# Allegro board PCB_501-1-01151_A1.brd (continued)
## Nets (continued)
SD1_CD#_R: R87.2 U6.J14
SD1_CLK: C93.1 J2.5 P5.2 R81.2
SD1_CLK_R: R81.1 U6.C1
SD1_CMD: J2.3 P6.2 R72.2 R82.2
SD1_CMD_R: R82.1 U6.C2
SD1_DATA0: R73.2 R107.1 U6.B3
SD1_DATA1: R74.2 R108.1 U6.B2
SD1_DATA2: R75.2 R105.1 U6.B1
SD1_DATA3: R76.2 R106.1 U6.A2
SD1_VSEL: R33.1 R35.1 R37.1 U4.B1
SD2_CLK: R71.2 U8.M6
SD2_CMD: R102.2 R830.1 U6.C8
SD2_DATA0: R94.2 R822.1 U6.D7
SD2_DATA1: R95.2 R823.1 U6.B7
SD2_DATA2: R96.2 R824.1 U6.A7
SD2_DATA3: R97.2 R825.1 U6.D6
SD2_DATA4: R98.2 R826.1 U6.C6
SD2_DATA5: R99.2 R827.1 U6.B6
SD2_DATA6: R100.2 R828.1 U6.A6
SD2_DATA7: R829.1 R858.2 U6.A5
SD2_RESET#: R101.2 U6.B4 U8.K5
SD2_STROBE: R103.2 U8.H5
SD_VSEL_R: R33.2 U6.D1
SDCARD_DAT0: J2.7 P4.2 R107.2
SDCARD_DAT1: J2.8 P3.2 R108.2
SDCARD_DAT2: J2.1 P8.2 R105.2
SDCARD_DAT3: J2.2 P7.2 R106.2
ST_HUB_LEDA1#: R150.1 U14.51
ST_HUB_LEDA2#: R151.1 U14.49
ST_HUB_LEDA3#: R153.1 U14.47
ST_HUB_LEDA4#: R157.1 U14.33
ST_HUB_LEDA5#: R158.1 U14.31
ST_QSPIA_SCLK: R809.1 U6.D5
ST_SD2_CLK: R71.1 U6.D8
STBY_REQ: Q41.3 R763.1 U1.26
SYS_BU: C33.1 U1.24
SYS_NRST: C599.1 D27.2 D28.2 R833.2 R874.2 U26.3
TOUCH_BUSY: R199.1 U6.G14
TOUCH_CLOCK: U6.E4 U24.16
TOUCH_CS#: R201.1 U6.E3
TOUCH_INTR_REQ#: U6.H15 U24.11
TOUCH_MISO: U6.E1 U24.12
TOUCH_MOSI: U6.E2 U24.14
TOUCH_X+: C191.2 R198.1 U24.2
TOUCH_X-: C192.2 R200.1 U24.4
TOUCH_XL: J9.38 R200.2
TOUCH_XR: J9.36 R198.2
TOUCH_Y+: C193.2 R202.1 U24.3
TOUCH_Y-: C194.2 R203.1 U24.5(Y-)
TOUCH_YD: J9.37 R203.2
TOUCH_YU: J9.39 R202.2
TPS2054_OC1#: R155.1 R816.1 U18.16
TPS2054_OC2#: R156.1 R817.1 U18.13
TPS2054_OC3#: R159.1 R818.1 U18.12
TPS2054_OC4#: R160.1 R819.1 U18.9
TXLED: D10.1(K) U20.7
UART1_CTS#: R832.2 U6.K15
UART1_RX_DATA: R167.1 R169.2 U6.K16
UART1_TX_DATA: R170.2 U6.K14
USB2ANY_I2C_SCL: H1.9 R875.2
USB2ANY_I2C_SDA: H1.10 R876.1
USB_HOST_DN: U6.T13 U14.58
USB_HOST_DP: U6.U13 U14.59
USB_HOST_ID: R770.2 U6.M17
USB_LDO_DECAP: C97.1 C98.1 U6.R12
USB_OTG1_CHD#: TP33.1 U6.U16
USB_OTG1_DN: FL6.1 U6.T15
USB_OTG1_DP: FL6.4 U6.U15
USB_OTG1_FAULT#: R86.2 U6.L15 U19.3
USB_OTG1_ID: J7.4 U6.K13 U17.4 U17.7
USB_OTG1_PWREN: R164.2 R166.1 U6.M16 U19.4
USBDM_FL1: FL1.2 J4.2 U15.5 U15.6
USBDM_FL2: FL2.2 J4.6 U15.2 U15.9
USBDM_FL3: FL3.2 J5.2 U16.5 U16.6
USBDM_FL4: FL4.2 J5.6 U16.2 U16.9
USBDM_FL5: FL5.2 J6.2 P15.2
USBDN: C176.1 R172.2 U20.9
USBDN1_DM: FL1.1 U14.1
USBDN1_DP: FL1.4 U14.2
USBDN2_DM: FL2.1 U14.3
USBDN2_DP: FL2.4 U14.4
USBDN3_DM: FL3.1 U14.6
USBDN3_DP: FL3.4 U14.7
USBDN4_DM: FL4.1 U14.8
USBDN4_DP: FL4.4 U14.9
USBDN5_DM: FL5.1 U14.11
USBDN5_DP: FL5.4 U14.12
USBDP: C175.1 R171.2 U20.8
USBDP_FL1: FL1.3 J4.3 U15.4 U15.7
USBDP_FL2: FL2.3 J4.7 U15.1 U15.10(NC4)
USBDP_FL3: FL3.3 J5.3 U16.4 U16.7
USBDP_FL4: FL4.3 J5.7 U16.1 U16.10(NC4)
USBDP_FL5: FL5.3 J6.3 P14.2
USR_B0: R872.2 SW4.2
USR_B1: R873.2 SW5.2
USR_BT0: C195.1 R204.2 R872.1 U6.F2
USR_BT1: C196.1 R208.2 R873.1 U6.F3
USR_LED1: R205.2 U6.D4
USR_LED2: R206.2 U6.D3
USR_LED3: R207.2 U6.D2
VREF_TOUCH_C: C189.2 U24.9
WDOG_ANY: R771.2 U6.M15 U27.2
X1_ENETPHY: R132.2 U10.70
XTALI: C204.1 R263.2 R821.2 U6.T16 X3.3
XTALIN_HUB: C129.1 R148.1 U14.61 X1.1
XTALO: C205.1 R263.1 U6.T17 X3.1
XTALOUT_HUB: C130.1 R148.2 U14.60 X1.3
N20222589: D5.2 R7.1
N20248573: R34.1 U4.A1
N20257520: R62.1 U7.L9
N20264538: FB16.2 J2.COM1 J2.COM2
N20269907: R17.2 R803.2 U2.4(Y)
N20274074: FB5.1 J8.5
N20274097: J8.4 R173.1
N20280334: D10.2 R176.2
N20280345: D11.2 R177.2
N20323615: R130.1 R133.1 Y1.1
N20326291: J3.32 R116.2
N20327026: D7.2 R109.2
N20327568: J3.28 R131.2
N20327935: D8.2 R124.2
N20368037: FB15.2 J7.5
N20387129: R225.1 SW6.5
N20387131: R226.1 SW6.6
N20387133: R227.1 SW6.7
N20387143: R232.1 SW6.8
N20387145: R575.2 SW7.4
N20387147: R576.2 SW7.3
N20429331: D28.1(K) R771.1 U27.4(Y)
N20436944: J3.1 J3.2 J3.3 J3.4 J3.8 J3.9 J3.10 R121.2
N20467513: R578.2 R579.1 U26.5
N20496187: J3.17 J3.18 J3.19(TRD4-[2]) J3.20 J3.24 J3.25 J3.26 R135.2
N20630241: DA8.3 R782.2
N20681531: C591.2 R790.2 R791.1 R810.1
N20684634: C592.2 R792.2 R793.1 R811.1
N20685468: C593.2 R794.2 R795.1 R812.1
N20685796: C594.2 R796.2 R797.1 R813.1
N20829804: D29.1(K) R266.2
N20866761: J3.33 R120.1
N20868982: J3.29 R134.2

Pads without a net: FD1 1; FD2 1; FD3 1; FD4 1; FD5 1; FD6 1; FD7 1; FD8 1; FD9 1; FD10 1; FD11 1; FD12 1; H1 1 2 3 4 5 7 8; J9 1 9 32 35; U1 28 29 34; U6 P16 P17; U8 A1 A2 A7 A8 A9 A10 A11 A12 A13 A14 B1 B7 B8 B9 B10 B11 B12 B13 B14 C1 C3 C5 C7 C8 C9 C10 C11 C12 C13 C14 D1 D2 D3 D4 D12 D13 D14 E1 E2 E3 E5 E8 E9 E10 E12 E13 E14 F1 F2 F3 F10 F12 F13 F14 G1 G2 G3 G10 G12 G13 G14 H1 H2 H3 H12 H13 H14 J1 J2 J3 J12 J13 J14 K1 K2 K3 K6 K7 K10 K12 K13 K14 L1 L2 L3 L12 L13 L14 M1 M2 M3 M7 M8 M9 M10 M11 M12 M13 M14 N1 N3 N6 N7 N8 N9 N10 N11 N12 N13 N14 P1 P2 P7 P8 P9 P10 P11 P12 P13 P14; U10 3 8 12 16 17 45 46 50 59 63 69 72 73 74 75 76 79; U14 14 15 16 17 18 32 36 37 38 39; U20 16; U22 8 9 10 13; U23 8 9 10 13; U24 8

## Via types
v1: diameter 0.457, hole 0.203, TOP to BOTTOM, 1517 vias

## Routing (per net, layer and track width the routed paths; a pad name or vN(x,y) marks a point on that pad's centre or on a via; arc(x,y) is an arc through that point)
3V3_OUT: length 2.2
  BOTTOM w0.142: R168.2 11.03,43.3 11.05,43.3 11.25,43.5 U20.10
5VIN: length 6.8
  TOP w0.381: R6.1 18.11,80.77 19.3,81.96 19.3,82.8 ; 22.61,88.77 22.75,88.77 R1.2 24.1,89.52 24.13,89.49 Q2.2
GND: length 1338.5
  TOP w0.076: U8.A6 73.8,24.06 73.77,24.06 ; U8.N5 79.72,23.63 79.32,23.63 v1(78.93,24.02) ; U8.N2 79.72,21.65 79.72,20.96
  TOP w0.142: U21.C2 8.31,41.33 v1(8.38,41.4) ; v1(79.72,20.83) 79.72,20.96 ; U8.K8 78.86,24.89 v1(78.99,25.02) ; U6.J5 v1(63.81,41.37) ; v1(73.15,25.08) 73.15,24.68 73.77,24.06
  TOP w0.178: P1.1 19.34,80.52 v1(19.32,80.49)
  TOP w0.203: v1(75.45,23.38) 75.45,23.37 U8.C4 ; v1(81.98,24.13) 81.07,24.13 80.83,23.89 U8.P6 U8.N5 ; v1(81.22,22.89) U8.P4 ; v1(61.41,38.97) 61.02,38.58 U6.E8 v1(60.61,38.97) ; v1(76.84,22.86) 76.97,22.99 U8.G5 ; v1(29.34,39.24) 29.45,39.24 29.6,39.39 U3.C1 ; v1(77.98,22.87) 77.97,22.88 U8.J5 ; U8.H10 v1(77.47,26.35) ; v1(76.71,24.77) 76.63,24.68 76.47,24.68 76.18,24.39 U8.E7 ; U4.C1 v1(92.07,22.48) ; U5.C1 v1(32.38,84.58) ; P14.1 46.72,83.29 v1(46.58,83.14) ; v1(60.61,44.6) 61,44.21 U6.M8 61.29,44.47 61.51,44.47 U6.M7 ; v1(46.41,85.33) 46.55,85.18 P15.1
  TOP w0.254: U7.T1 v1(77.81,33.61) ; U6.R16 v1(54.18,47) ; U6.U1 67.26,48.18 67.31,48.13 v1(67.31,48.17) ; v1(53.72,48.64) 53.72,48.26 U6.U17 ; U6.N7 v1(62.21,45.4) ; U6.L12 v1(57.38,43.8) ; U6.T14 v1(55.78,47.8) ; v1(78.36,79.12) U15.3 U15.8 v1(80.65,79.12) ; v1(59.81,38.97) U6.F10 59.26,39.24 58.74,39.24 U6.F11 58.6,39.29 58.42,39.11 58.06,39.11 57.8,39.38 U6.F12 v1(57.38,38.97) ; U7.P1 v1(77.81,35.21) ; U7.D8 v1(84.21,44) ; v1(59.69,79.25) U16.8 U16.3 v1(62.1,79.25) ; U7.G1 v1(77.81,41.6) ; U6.R7 v1(62.21,47) ; U6.K7 v1(62.21,43) ; U6.E11 v1(58.18,38.17) ; U7.G9 v1(85.01,41.6) ; U26.2 v1(91.69,81.91) ; U7.G8 v1(84.21,41.6) ; U6.M9 v1(60.61,44.6) ; U7.M9 v1(85.01,36.81) ; U6.G3 v1(65.41,39.77) ; v1(5.46,30.99) U17.8 U17.3 v1(5.46,28.58) ; U6.G5 v1(63.81,39.77) ; U6.M11 58.21,44.57 v1(58.16,44.57) 57.8,44.21 U6.M12 ; U7.J2 v1(78.61,39.21) ; U6.C7 v1(62.21,36.57) ; U6.H7 v1(62.21,40.57) ; U6.N3 v1(65.41,45.4) ; U6.L3 v1(65.41,43.8) ; U7.E8 v1(84.21,43.2) ; U6.G7 v1(62.21,39.77) ; v1(53.45,46.97) 53.47,46.96 53.47,46.91 U6.R17 ; U7.D1 v1(77.81,44) ; U7.M1 v1(77.81,36.81) ; U6.R11 v1(58.18,47) ; U6.M7 v1(62.21,44.6) ; U6.R3 v1(65.41,47) ; U6.F9 v1(60.61,38.97) ; U6.A1 v1(66.99,34.99) ; U6.C3 v1(65.41,36.57) ; U6.A17 v1(53.38,34.97) ; U6.F7 v1(62.21,38.97) ; U6.U14 v1(55.78,48.6) ; U7.E2 v1(78.61,43.2) ; U6.J7 v1(62.21,41.37) ; U6.L7 v1(62.21,43.8) ; U7.B1 v1(77.81,45.6) ; U7.B9 v1(85.01,45.6) ; U6.H12 57.77,40.98 v1(57.38,41.37) U6.J12 ; U7.E1 v1(77.81,43.2) ; U6.F6 v1(63.01,38.97) ; U7.J8 v1(84.21,39.21) ; U6.N5 v1(63.81,45.4) ; U6.C11 v1(58.18,36.57) ; U6.M10 v1(58.98,44.6) ; U14.19 v1(67.27,72.09) ; U6.K12 v1(57.38,43) ; U26.6 v1(92.19,80.01) ; U7.B3 v1(79.41,45.6) ; U6.G15 v1(54.98,39.77) ; U6.G12 v1(57.38,39.77) ; U6.F8 v1(61.41,38.97) ; U7.P9 v1(85.01,35.21) ; U6.R5 v1(62.98,47) ; U6.C15 v1(54.98,36.57) ; U7.F9 v1(85.01,42.4) ; U7.A9 v1(85.01,46.4) ; U7.T9 v1(85.01,33.61)
  TOP w0.305: v1(46.22,48.14) 46.1,48.26 C9.2 ; C18.2 45.8,49.4 46.08,49.69 v1(46.13,49.69)
  TOP w0.381: 76.61,57.75 C589.2 v1(76.71,56.52) ; 76.61,57.75 76.07,57.21 v1(76.07,56.64) ; 76.61,57.75 v1(75.6,57.75) ; C115.2 v1(96.14,18.41) ; H4.11 19.72,43.94 v1(20.32,44.55) ; v1(51.16,61.99) 51.67,62.5 R15.1 ; 1.4,22.34 J7.S4 v1(4.26,22.34) ; H4.17 v1(19.94,40.13) ; C3.2 26.01,71.6 v1(26.39,71.22) ; v1(28.45,73.91) C4.2 v1(27.43,75.02) ; SW8.1 98.75,79.07 v1(98.55,78.87) ; TP32.1 v1(43.43,76.2) ; SW4.3 v1(97.1,54.03) ; R851.1 R852.1 v1(13.97,61.85) ; v1(52.07,60.07) 52.07,60.02 52.32,59.77 52.32,59.47 C23.2 53.09,59.65 v1(53.09,60.07) ; v1(21.46,71.22) 19.3,71.22 C590.2 ; v1(35.81,58.84) C24.2 v1(37.71,58.84) ; R62.2 v1(89.41,38.1) ; H4.13 19.37,42.67 19.73,42.32 v1(19.79,42.32) ; R149.2 v1(80.42,63.25) ; v1(75.69,63.12) 75.69,63 75.16,62.46 R152.2 ; C33.2 v1(38.48,62.87) ; SW3.1 v1(96.47,73.99) ; v1(82.8,80.77) 83.08,80.5 83.25,80.5 ; C41.2 v1(29.21,84.71) 29.08,84.58 28.32,84.58 27.82,84.08 D5.1 ; R146.2 v1(71.25,58.01) ; C177.2 v1(4.06,47.12) ; v1(79.4,56.69) 79.74,57.03 C597.2 ; C114.2 97.41,20.07 97.72,20.38 v1(97.72,21.4) ; R178.2 v1(2.79,47.12) ; C599.2 v1(94.74,82.8) ; R253.1 v1(45.59,26.19) ; v1(40.01,19.56) 40.02,19.54 C116.2 v1(40.89,18.8) ; R14.2 v1(39.75,68.96) ; C591.1 37.21,18.16 v1(37.47,17.91) ; C588.2 v1(20.96,44.96) ; C598.2 95.87,77.62 v1(95.25,78.23) ; v1(33.02,84.96) 33.66,84.33 C43.2 ; X3.4 50.11,54.65 v1(49.66,55.1) ; C190.2 64.79,16.24 v1(64.9,16.13) ; U2.3 53.99,60.06 53.84,60.21 v1(53.72,60.21) ; R16.2 v1(54.74,64.17) ; C126.2 v1(40.89,22.86) ; D1.2 v1(23.88,91.69) ; v1(36.55,13.57) 36.6,13.62 ; v1(79.4,58.34) 79.74,58 C597.2 ; v1(50.8,49.15) 50.67,49.15 50.55,49.28 C8.2 C7.2 ; DA1.4 v1(91.04,97.93) ; H5.8 v1(1.9,59.31) ; R770.1 v1(43.43,39.24) ; v1(59.05,8.64) 59.56,8.13 C184.2 ; C586.2 v1(22.1,47.75) ; R154.2 67.18,61.91 67.13,61.86 67.13,61.67 v1(66.93,61.47) ; C186.2 v1(68.58,3.56) ; v1(4.32,24.65) J7.S3 1.41,24.65 ; v1(36.96,60.85) C29.2 37.36,61.34 37.2,61.34 37.17,61.37 37.05,61.37 v1(36.96,61.46) ; R254.1 v1(50.16,26.19) ; R843.1 v1(92.84,69.85) ; v1(46.77,26.23) 46.74,26.19 R260.1 ; C129.2 v1(78.94,73.3) ; J7.S2 v1(4.26,19.74) ; Q3.2 v1(14.84,80.12) ; R127.1 v1(45.59,18.92) ; R19.2 v1(54.48,64.87) ; C198.2 v1(84.47,8.15) ; v1(49.53,66.8) 48.96,66.23 C19.2 v1(49.78,65.79) ; v1(96.01,75.44) 96.27,75.69 SW3.3 ; v1(93.6,22.23) 93.49,22.34 C39.2 ; H4.15 v1(19.94,41.4) ; v1(30.1,75.06) C5.2 v1(30.84,75.8) ; R63.1 v1(89.41,36.96) ; C11.2 36.39,49.66 v1(36.29,49.56) ; C34.2 v1(37.57,55.12) ; C95.2 C94.2 56.75,51.82 56.37,52.2 v1(56.26,52.2) ; C36.2 v1(31.48,41.55) ; v1(30.05,38.27) 30.4,38.27 30.52,38.16 30.55,38.16 30.63,38.08 R805.2 ; v1(22.86,61.85) 22.1,61.09 H1.6 ; J7.S1 v1(4.26,27.25) ; H5.12 v1(1.9,64.39) ; C20.2 v1(48.77,67.44) ; H5.16 v1(1.9,69.47) ; C21.2 v1(50.42,55.63) ; C127.2 v1(42.04,22.86) ; C195.2 v1(92.71,52.2) ; H5.4 v1(1.9,54.23) ; H5.14 1.8,66.93 1.78,66.95 v1(1.71,66.95) ; v1(37.64,23.95) 37.31,24.29 C593.1 ; v1(41.58,68.59) C31.2 v1(40.81,68.8) ; DA2.4 v1(72.12,97.93) ; v1(76.71,75.22) 76.71,74.11 R577.1 ; C130.2 v1(78.21,69.86) ; C583.2 v1(23.24,52.2) ; v1(88.26,80.52) 88.52,80.77 C573.2 ; C183.2 C187.2 C185.2 C182.2 v1(62.48,3.43) ; C32.2 v1(37.08,65.58) ; R848.1 v1(12.85,73.15) ; v1(43.69,71.12) C30.2 v1(42.76,70.14) ; R259.1 v1(49.02,26.19) ; C572.2 v1(3.67,48.24) ; v1(95.12,81.03) 94.62,81.53 R579.2 ; R37.2 90.91,19.79 v1(91.06,19.94) ; SW4.1 v1(97.41,51.39) ; v1(95.88,58.42) 96.7,57.61 SW5.1 ; v1(1.56,61.83) 1.65,61.83 1.67,61.85 H5.10 ; C164.2 v1(62.74,71.63) ; C120.2 50.99,17.67 v1(51.05,17.61) 51.63,17.61 51.68,17.56 C117.2 ; R144.2 v1(71.88,61.6) ; R258.1 v1(47.88,26.19) ; C93.2 71.37,31.6 v1(70.87,31.1) ; TP30.1 v1(86.76,74.29) ; H4.19 v1(19.94,38.86) ; SW2.3 v1(96.01,69.72) ; FB15.1 v1(4.59,16.87) ; C596.2 v1(30.48,84.71) ; U27.3 v1(93.08,89.52) ; v1(55.88,52.7) 55.31,52.7 54.97,53.05 X3.2 53.69,52.65 C204.2 ; C22.2 52.67,56.37 v1(52.7,56.34) ; H5.6 v1(1.9,56.77) ; Q17.2 19.23,54.17 v1(19.81,53.59) ; R58.2 v1(89.41,40.39) ; C197.2 v1(78.36,3.43) ; R60.2 v1(89.41,39.24) ; R257.1 v1(43.31,26.19) ; FB5.2 v1(9.56,37.47) ; R256.1 v1(44.45,26.19) ; C597.2 v1(78.99,57.53) ; C174.2 v1(7.33,44.79) ; DA3.4 v1(68.69,97.93) ; SW2.1 v1(96.44,68.02) ; C35.2 v1(34.18,41.55) ; v1(95.76,82.55) 95.76,81.98 96.08,81.66 SW8.3 ; DA5.4 v1(36.94,97.93) ; DA8.4 v1(24.98,53.3) ; R255.1 v1(51.31,26.19) ; v1(56.52,54.61) 55.73,53.83 R821.1 ; C161.2 v1(62.71,65.02) ; C162.2 v1(62.71,67.31) ; C584.2 v1(22.1,50.67) ; v1(88.9,25.27) 89.05,25.42 C40.2 C42.2 v1(91.83,25.42) ; DA4.4 v1(49.64,97.93) ; H5.18 v1(1.9,72.01) ; C10.2 v1(36.29,50.93) ; R145.2 v1(70.76,60.22) ; v1(94.33,25.4) FB16.1 v1(94.98,26.05) ; v1(92.84,58.8) 93.34,59.31 C196.2 ; H5.20 v1(1.9,74.55) ; C587.2 v1(22.1,44.96) ; R17.1 v1(57.02,57.15) ; C585.2 v1(22.1,48.9) ; R173.2 v1(9.56,38.61) ; R135.1 v1(24.51,37.72) ; v1(50.93,50.93) 50.57,51.28 C205.2 ; C38.2 v1(28.32,42.29) ; TP31.1 v1(42.8,5.84) ; SW5.3 v1(95.88,59.31) ; C199.2 v1(79.5,3.43) ; R9.1 v1(14.08,76.33) ; C1.2 v1(17.14,81.9) ; C163.2 v1(62.74,69.34)
  TOP w0.508: J3.S2 26.89,24.37 ; J3.S2 25.3,22.79 ; J3.S2 28.47,22.79 ; 73.75,87.32 J4.S4 ; J4.S4 73.75,91.74 ; J4.S4 75.96,89.53 ; 78.79,70.51 C130.2 77.64,70.51 ; J6.S3 44.12,82.41 ; J6.S3 42.69,80.98 ; J6.S3 45.56,80.98 ; H5.18 6.4,72.01 ; H5.18 4.26,71.07 ; H5.18 4.26,72.95 ; J6.S1 44.12,89.41 ; J6.S1 44.12,86.54 ; J6.S1 45.56,87.98 ; J6.S1 42.69,87.98 ; 77.65,73.3 C129.2 78.22,73.87 ; 5.01,86.11 J1.2 ; J1.2 7.63,86.11 ; J1.2 6.32,88.48 ; J1.2 6.32,83.73 ; J6.S2 38.68,89.41 ; J6.S2 40.12,87.98 ; J6.S2 38.68,86.54 ; 86.89,86.06 J4.S2 86.89,81.64 ; MH5.1 36.07,78.6 ; MH5.1 38.47,76.2 ; MH5.1 36.07,73.8 ; MH5.1 33.67,76.2 ; H5.12 6.4,64.39 ; H5.12 4.26,65.33 ; H5.12 4.26,63.45 ; 64.54,87.32 J5.S3 ; J5.S3 62.33,89.53 ; J5.S3 66.75,89.53 ; J5.S3 64.54,91.74 ; 40.32,81.25 J6.4 ; J6.4 42.48,81.25 ; J6.4 41.4,80.17 ; 86.89,87.32 J4.S3 ; J4.S3 84.68,89.53 ; J4.S3 89.1,89.53 ; J4.S3 86.89,91.74 ; 95.4,18.99 C115.2 95.4,17.84 ; 83.25,80.5 C601.1 ; C601.1 84.39,80.5 ; C601.1 83.82,79.93 ; 1.49,27.25 J7.S1 2.75,28.71 ; 28.36,94.16 TP56.1 ; TP56.1 27.04,96.37 ; TP56.1 28.36,98.58 ; TP56.1 29.68,96.37 ; 5.59,16.3 FB15.1 6.16,16.87 ; J3.S3 26.89,8.01 ; J3.S3 25.3,6.43 ; J3.S3 28.47,6.43 ; 4.64,46.25 C177.2 3.49,46.25 ; 91.44,5.07 MH6.1 89.04,2.67 ; 89.04,76.2 MH7.1 ; MH7.1 91.44,73.8 ; MH7.1 93.84,76.2 ; 73.75,86.06 J4.S1 73.75,81.64 ; J3.S4 11.68,6.43 ; J3.S4 10.1,8.01 ; J3.S4 8.51,6.43 ; 96.71,19.1 C114.2 96.05,20.07 ; 64.54,81.64 J5.S2 ; J5.S2 64.54,86.06 ; J5.S2 66.75,83.85 ; 4.26,60.91 H5.10 ; H5.10 4.26,62.79 ; H5.10 6.4,61.85 ; J5.8 55.55,86.82 ; J5.8 54.47,85.74 ; J5.8 54.47,87.9 ; J5.8 53.39,86.82 ; J3.S1 11.68,22.79 ; J3.S1 10.1,24.37 ; J3.S1 8.51,22.79 ; 41.78,5.03 TP31.1 ; TP31.1 41.78,6.66 ; TP31.1 40.97,5.84 ; 83.57,8.72 C198.2 82.99,8.15 ; 7.33,42.75 C174.2 6.54,43.56 ; 21.59,94.6 SW1.S2 ; SW1.S2 22.88,96.27 ; SW1.S2 21.59,97.93 ; 48.03,67.86 C20.2 48.03,67.02 ; 36.57,13.72 C592.1 37.14,14.29 ; 93.49,23.94 C39.2 94.06,23.37 ; 76.59,74.56 R577.1 77.16,73.99 ; J4.8 76.82,87.9 ; J4.8 75.74,86.82 ; J4.8 77.9,86.82 ; J4.8 76.82,85.74 ; 4.26,68.53 H5.16 ; H5.16 6.4,69.47 ; H5.16 4.26,70.41 ; H5.8 6.4,59.31 ; H5.8 4.26,60.25 ; H5.8 4.26,58.37 ; 4.32,47.67 C572.2 4.89,48.24 ; MH8.1 38.47,2.67 ; MH8.1 33.67,2.67 ; MH8.1 36.07,5.07 ; 39.33,69.7 R14.2 40.17,69.7 ; 19.49,97.4 SW1.3 19.49,95.14 ; J1.S2 5.32,91.91 ; J1.S2 5.32,89.3 ; J1.S2 2.77,90.61 ; J1.S2 7.87,90.61 ; H5.6 4.26,57.71 ; H5.6 6.4,56.77 ; H5.6 4.26,55.83 ; H5.20 4.26,75.49 ; H5.20 4.26,73.61 ; H5.20 6.4,74.55 ; 87.58,73.19 TP30.1 86.76,72.38 ; 42.16,77.01 TP32.1 42.16,75.39 ; 1.49,19.74 J7.S2 2.75,18.28 ; J1.S1 7.87,81.61 ; J1.S1 5.32,82.91 ; J1.S1 2.77,81.61 ; J1.S1 5.32,80.3 ; 49.19,83.85 J5.S1 ; J5.S1 51.4,81.64 ; J5.S1 51.4,86.06 ; 17.49,97.4 SW1.2 17.49,95.14 ; 12.11,96.27 SW1.S1 ; SW1.S1 13.39,94.6 ; SW1.S1 13.39,97.93 ; 29.78,83.97 C41.2 28.64,83.97 ; J6.S4 40.12,80.98 ; J6.S4 38.68,82.41 ; J6.S4 38.68,79.54 ; 76.82,85.28 J4.4 76.82,83.12 ; J5.S4 51.4,91.74 ; J5.S4 51.4,87.32 ; J5.S4 53.61,89.53 ; 27.82,83.06 D5.1 28.63,83.82 ; 3.37,46.25 R178.2 2.22,46.25 ; 6.4,66.93 H5.14 4.26,67.87 ; 54.47,85.28 J5.4 54.47,83.12 ; H5.4 4.26,55.17 ; H5.4 6.4,54.23 ; H5.4 4.26,53.29 ; 13.42,64.39 R851.1 12.85,64.96 ; 36.21,29.72 C594.1 36.79,29.15 ; 40.81,67.16 C31.2 41.44,67.82
  L2_GND w0.508: J5.S4 53.61,89.53 ; J5.S4 51.4,91.74 ; J5.S4 49.19,89.53 ; J5.S4 51.4,87.32 ; 96.77,5.36 MH2.1 94.72,3.3 ; J5.8 55.55,86.82 ; J5.8 53.39,86.82 ; J5.8 54.47,87.9 ; J5.8 54.47,85.74 ; 71.54,89.53 J4.S4 ; J4.S4 73.75,91.74 ; J4.S4 73.75,87.32 ; J4.S4 75.96,89.53 ; 91.44,74.64 MH7.1 ; MH7.1 91.44,77.76 ; MH7.1 93,76.2 ; MH7.1 89.88,76.2 ; 44.12,79.54 J6.S3 ; J6.S3 42.69,80.98 ; J6.S3 45.56,80.98 ; J6.S3 44.12,82.41 ; J4.S1 73.75,86.06 ; J4.S1 73.75,81.64 ; J4.S1 71.54,83.85 ; J6.S4 38.68,82.41 ; J6.S4 37.25,80.98 ; J6.S4 40.12,80.98 ; J6.S4 38.68,79.54 ; J4.4 77.9,84.2 ; J4.4 76.82,83.12 ; J4.4 76.82,85.28 ; 41.4,80.17 J6.4 ; J6.4 40.32,81.25 ; J6.4 42.48,81.25 ; 25.3,22.79 J3.S2 ; J3.S2 26.89,21.2 ; J3.S2 28.47,22.79 ; J3.S2 26.89,24.37 ; J1.2 7.63,86.11 ; J1.2 6.32,83.73 ; J1.2 6.32,88.48 ; J1.2 5.01,86.11 ; 8.51,22.79 J3.S1 ; J3.S1 11.68,22.79 ; J3.S1 10.1,21.2 ; J3.S1 10.1,24.37 ; 37.25,87.98 J6.S2 ; J6.S2 40.12,87.98 ; J6.S2 38.68,89.41 ; J6.S2 38.68,86.54 ; J3.S3 28.47,6.43 ; J3.S3 25.3,6.43 ; J3.S3 26.89,8.01 ; J3.S3 26.89,4.84 ; J3.S4 10.1,8.01 ; J3.S4 10.1,4.84 ; J3.S4 11.68,6.43 ; J3.S4 8.51,6.43 ; 89.88,2.67 MH6.1 ; MH6.1 91.44,4.23 ; MH6.1 93,2.67 ; MH5.1 36.07,77.76 ; MH5.1 36.07,74.64 ; MH5.1 34.51,76.2 ; MH5.1 37.63,76.2 ; 5.32,89.3 J1.S2 ; J1.S2 2.77,90.61 ; J1.S2 7.87,90.61 ; J1.S2 5.32,91.91 ; 3.18,94.72 MH1.1 5.23,96.77 ; 34.51,2.67 MH8.1 ; MH8.1 36.07,4.23 ; MH8.1 37.63,2.67 ; 5.23,3.3 MH3.1 3.18,5.36 ; 96.77,94.72 MH4.1 94.72,96.77 ; 62.33,89.53 J5.S3 ; J5.S3 64.54,91.74 ; J5.S3 66.75,89.53 ; J5.S3 64.54,87.32 ; 42.69,87.98 J6.S1 ; J6.S1 44.12,86.54 ; J6.S1 44.12,89.41 ; J6.S1 45.56,87.98 ; 17.49,95.36 SW1.2 ; SW1.2 17.49,97.17 ; SW1.2 18.4,96.27 ; SW1.2 16.59,96.27 ; J4.S3 89.1,89.53 ; J4.S3 86.89,91.74 ; J4.S3 86.89,87.32 ; J4.S3 84.68,89.53 ; SW1.S2 22.84,96.27 ; SW1.S2 21.59,95.02 ; SW1.S2 21.59,97.51 ; 51.4,81.64 J5.S1 ; J5.S1 51.4,86.06 ; J5.S1 49.19,83.85 ; J4.S2 86.89,86.06 ; J4.S2 89.1,83.85 ; J4.S2 86.89,81.64 ; J5.4 55.55,84.2 ; J5.4 54.47,85.28 ; J5.4 54.47,83.12 ; J5.S2 64.54,86.06 ; J5.S2 64.54,81.64 ; J5.S2 66.75,83.85 ; 19.49,95.36 SW1.3 ; SW1.3 18.59,96.27 ; SW1.3 19.49,97.17 ; J4.8 77.9,86.82 ; J4.8 75.74,86.82 ; J4.8 76.82,85.74 ; J4.8 76.82,87.9 ; 5.32,80.3 J1.S1 ; J1.S1 7.87,81.61 ; J1.S1 5.32,82.91 ; J1.S1 2.77,81.61 ; SW1.S1 13.39,97.51 ; SW1.S1 12.15,96.27 ; SW1.S1 13.39,95.02
  L3_SIG1 w0.508: 2.77,81.61 J1.S1 ; J1.S1 5.32,82.91 ; J1.S1 5.32,80.3 ; J1.S1 7.87,81.61 ; 2.77,90.61 J1.S2 ; J1.S2 5.32,91.91 ; J1.S2 7.87,90.61 ; J1.S2 5.32,89.3 ; J1.2 7.63,86.11 ; J1.2 6.32,88.48 ; J1.2 6.32,83.73 ; J1.2 5.01,86.11
  L4_SIG2 w0.508: 6.32,83.73 J1.2 ; J1.2 5.01,86.11 ; J1.2 6.32,88.48 ; J1.2 7.63,86.11 ; J1.S2 5.32,91.91 ; J1.S2 7.87,90.61 ; J1.S2 5.32,89.3 ; J1.S2 2.77,90.61 ; 5.32,80.3 J1.S1 ; J1.S1 7.87,81.61 ; J1.S1 2.77,81.61 ; J1.S1 5.32,82.91
  L5_PWR w0.381: v1(96.65,22.22) 95.16,22.22 94.95,22.01
  L5_PWR w0.508: MH6.1 91.44,4.23 ; MH6.1 89.88,2.67 ; MH6.1 93,2.67 ; 5.32,89.3 J1.S2 ; J1.S2 7.87,90.61 ; J1.S2 5.32,91.91 ; J1.S2 2.77,90.61 ; 25.3,22.79 J3.S2 ; J3.S2 28.47,22.79 ; J3.S2 26.89,24.37 ; J3.S2 26.89,21.2 ; 6.32,83.73 J1.2 ; J1.2 7.63,86.11 ; J1.2 5.01,86.11 ; J1.2 6.32,88.48 ; J3.S1 11.68,22.79 ; J3.S1 8.51,22.79 ; J3.S1 10.1,24.37 ; J3.S1 10.1,21.2 ; 10.1,4.84 J3.S4 ; J3.S4 10.1,8.01 ; J3.S4 11.68,6.43 ; J3.S4 8.51,6.43 ; 25.3,6.43 J3.S3 ; J3.S3 26.89,8.01 ; J3.S3 28.47,6.43 ; J3.S3 26.89,4.84 ; 5.23,3.3 MH3.1 3.18,5.36 ; J1.S1 7.87,81.61 ; J1.S1 5.32,82.91 ; J1.S1 2.77,81.61 ; J1.S1 5.32,80.3 ; 34.51,2.67 MH8.1 ; MH8.1 36.07,4.23 ; MH8.1 37.63,2.67 ; 96.77,5.36 MH2.1 94.72,3.3
  BOTTOM w0.142: v1(58.18,47) 58.33,47 58.75,47.42 59.27,47.42 59.59,47.1 C60.2
  BOTTOM w0.178: P5.1 v1(88.39,27.43) ; P7.1 v1(85.72,27.43) ; P4.1 v1(89.66,27.43) ; P8.1 v1(84.33,27.43) ; P6.1 v1(87,27.43) ; P3.1 v1(91.06,27.43)
  BOTTOM w0.203: J9.40 54,6.05 v1(53.85,6.2) ; P10.1 82.8,79.08 v1(82.38,79.08) ; C577.2 47.77,13.09 47.72,13.15 U10.6 47.72,14.9 47.68,14.93 v1(47.68,15.08) ; v1(51.05,17.61) 51.21,17.45 U10.77 ; P2.1 v1(81.03,18.41) ; v1(40.01,19.56) 39.61,19.95 U10.29 ; P9.1 v1(93.7,85.85) ; v1(57.01,78.64) 57.2,78.82 P12.1 ; U10.33 39.73,21.95 v1(40.01,22.23) ; U10.22 v1(40.07,16.45)
  BOTTOM w0.254: v1(53.45,46.97) 53.44,46.99 53.34,46.99 53.09,46.74 C56.2 ; U13.2 U13.1 ; U13.2 U13.3 ; U13.2 83.69,61.22 ; U13.1 84.19,60.72 83.69,61.22 ; U13.1 v1(84.19,59.18) ; U10.55 47.72,28.42 v1(47.75,28.45) ; v1(45.47,15.37) 45.72,15.12 U10.10 ; C122.1 U11.8 U11.3 v1(31.75,16.26) ; U13.3 v1(83.19,59.18) ; U13.3 83.19,61.22 ; U13.3 U13.4 82.69,60.72 83.19,61.22 ; J9.6 71,4.03 71.02,4.01 71.02,3.7 71.21,3.51 v1(71.21,3.21) ; v1(70.61,3.34) 70.61,3.85 70.5,3.96 J9.7 ; U10.64 53.02,23.95 v1(53.2,24.13) ; P11.1 60.12,78.82 v1(59.69,79.25) ; C61.2 61.31,47.1 v1(61.41,47) ; U10.29 37.96,19.95 37.57,20.34 C575.2 ; v1(73.81,72.92) 73.81,73.2 C138.2 ; v1(73.91,3.89) 73.27,3.89 73.05,4.11 73.05,4.3 73.04,4.31 73.04,4.41 73,4.46 J9.2 ; 83.19,61.22 v1(83.44,61.47) 83.69,61.22 ; v1(54.18,47) 54.1,46.91 C55.2 ; J9.4 72.04,4.99 72.04,4.12 72.14,4.03 72.14,3.4 v1(72.26,3.27) ; U10.37 v1(37.64,23.95) ; v1(46.77,26.23) 46.42,26.23 46.22,26.43 U10.52 ; v1(71.63,3.82) 71.5,3.95 J9.5 ; v1(57.38,39.77) 57.43,39.82 C91.2 ; v1(83.67,65) C128.2 83.67,63.59 83.69,63.57 U13.7 ; U12.8 v1(31.24,27.94) ; v1(69.74,3.3) 70,3.56 J9.8 ; U10.40 39.68,25.45 v1(39.88,25.65) ; P13.1 v1(45.59,76.2) ; U20.5 v1(16.18,44.77) ; U10.25 v1(39.96,17.95) ; U12.3 v1(28.58,27.94)
  BOTTOM w0.305: v1(73.66,69.47) 73.91,69.72 C140.2 ; C139.2 v1(70.1,72.26) ; C142.2 v1(72.52,72.26) ; C143.2 v1(73.79,68.2) ; C135.2 v1(67.82,67.82) ; v1(30.99,49.78) 30.99,49.25 31.19,49.05 U22.3 ; U23.3 v1(32.08,69.92) ; C136.2 v1(67.82,68.96) ; C141.2 v1(73.79,67.06) ; R147.2 v1(68.58,72.26)
  BOTTOM w0.381: C72.2 62.88,47.1 v1(62.98,47) ; C574.2 v1(47.64,29.98) ; C607.2 v1(59.27,15.25) ; C605.1 44.01,75.62 v1(43.43,76.2) ; R238.1 63.01,11.7 v1(63.22,11.91) ; R246.1 73.79,14.62 74.17,15.01 v1(74.17,15.11) ; v1(53.45,18.54) 53.54,18.45 Y1.2 v1(54.64,19.84) ; C134.2 v1(73.53,70.99) ; C189.1 65.15,19.61 64.77,19.23 v1(64.77,18.92) ; R64.1 v1(80.39,35.69) ; v1(55.7,10.49) 55.63,10.41 C192.1 ; U9.4 70.75,30.99 v1(70.87,31.1) ; R251.1 v1(77.34,13.84) ; R572.2 v1(51.31,10.54) ; C121.2 v1(44.72,29.86) ; C201.2 v1(60.38,54.03) ; C85.2 85.06,33.55 v1(85.01,33.61) ; R197.2 v1(80.26,11.16) ; v1(43.56,74.8) 43.56,74.04 TP42.1 ; v1(57.38,38.97) 57.65,38.71 C47.2 58.01,38.34 v1(58.18,38.17) ; R239.1 v1(63.25,10.92) ; C109.2 81.21,22.88 v1(81.22,22.89) ; v1(57.53,81.41) 57.53,80.72 57.48,80.67 C604.1 ; v1(59.05,8.64) R194.2 ; v1(47.99,66.44) R24.1 R21.2 ; C172.2 v1(20.96,38.99) ; v1(35.13,38.48) 33.79,38.48 33.51,38.76 R569.1 ; C92.2 65.68,36.3 v1(65.41,36.57) 65.91,37.06 C96.2 ; v1(65.41,39.77) 65.89,39.77 66.06,39.6 C68.2 C67.2 ; v1(96.27,67.18) 95.88,67.56 C149.2 ; C180.2 v1(32.66,50.31) ; R129.2 v1(34.06,20.96) ; R248.1 v1(75.06,15.37) ; C153.2 v1(87.08,70.19) ; v1(96.14,60.07) 96.05,60.16 U18.1 ; v1(85.01,36.81) 85.11,36.91 C63.2 ; v1(70.37,46.27) 70.21,46.1 C54.2 ; C125.1 v1(7.73,29.73) ; C78.2 85.06,46.46 v1(85.01,46.4) ; R242.1 70.41,14.91 70.76,15.27 v1(70.76,15.29) ; U20.13 10.77,45.4 10.43,45.74 C171.2 10.16,46.23 v1(9.91,46.48) ; v1(62.21,39.77) C69.2 v1(62.21,40.57) 62.13,40.65 62.13,40.95 C52.2 62.14,41.3 v1(62.21,41.37) 62.12,41.46 C51.2 62.12,42.91 v1(62.21,43) v1(62.21,43.8) C70.2 v1(62.21,44.6) ; v1(62.21,38.97) 62.39,38.79 C90.2 ; R808.2 v1(81.03,12.45) ; v1(4.95,50.42) C37.2 5.7,51.03 4.01,52.71 4.01,57.61 BH1.2 ; C77.2 85.11,41.5 v1(85.01,41.6) ; R773.1 51.17,37.19 v1(50.87,37.49) ; C575.2 v1(36.32,20.34) ; R240.1 68.83,14.75 v1(68.83,15.37) ; v1(65.49,50.21) 65.66,50.04 C88.2 ; v1(77.85,2.57) 77.62,2.33 J9.M1 75.6,2.8 v1(76.53,3.73) ; C49.2 v1(49.38,42.16) ; R245.1 v1(72.64,13.84) ; C158.2 v1(95.88,58.42) ; C193.1 v1(53.72,9.8) ; Q41.2 v1(33.81,64.45) ; U19.6 52.96,71.75 v1(53.34,72.14) ; v1(62.23,16.64) 62.02,16.85 U24.6 ; R236.1 v1(61.6,10.92) ; C156.2 v1(83.69,67.31) ; v1(77.81,35.21) 77.37,34.77 C74.2 ; v1(29.21,84.71) 29.44,84.94 R806.2 ; v1(77.98,22.87) 77.98,22.86 78.21,22.63 C108.2 ; C603.1 60.11,80.13 60.11,80.88 v1(60.16,80.93) ; v1(30.21,37.59) 30.23,37.59 30.61,37.97 R836.2 ; R247.1 v1(74.29,13.84) ; v1(82.17,25.15) 82.15,25.17 C107.2 ; C191.1 v1(57.91,10.45) ; v1(56.26,52.2) 56.62,51.84 C97.2 C98.2 ; R121.1 v1(14.73,23.88) ; v1(9.3,40.93) 9.58,40.65 9.69,40.65 ; C83.2 77.41,46 v1(77.81,45.6) ; R241.1 v1(69.6,13.97) ; R174.1 21.72,43.56 v1(21.75,43.59) ; C131.2 v1(67.94,71.25) ; C168.2 v1(53.78,69.78) ; C124.1 v1(6.98,27.69) ; R65.2 65.88,45.87 v1(65.41,45.4) ; v1(77.81,41.6) 77.55,41.87 77.55,41.87 77.43,41.98 77.43,41.98 77.36,42.06 C64.2 ; C576.2 v1(36.34,21.57) ; C76.2 83.54,42.27 v1(84.21,41.6) ; C154.2 v1(87.86,71.39) ; C104.2 79.01,25 v1(78.99,25.02) ; v1(55.78,48.6) v1(55.78,47.8) ; R772.2 30.48,41.29 v1(30.84,41.66) ; v1(58.16,44.57) 58.18,44.6 C53.2 v1(58.98,44.6) 59.11,44.47 C45.2 60.48,44.47 v1(60.61,44.6) ; R252.1 v1(78.87,14.62) ; C200.2 60.4,50.56 60.81,50.56 v1(61.13,50.88) ; v1(85.01,42.4) 85.17,42.57 C80.2 ; v1(65.41,43.8) 66.38,43.8 C71.2 ; C87.2 v1(67.72,52.83) ; R249.1 v1(75.82,13.84) ; C155.2 v1(85.09,66.54) ; C122.1 28.85,16.74 28.7,16.89 v1(28.7,16.9) ; C166.2 v1(49.78,77.09) ; C133.2 v1(67.94,70.1) ; v1(50.62,39.53) 50.87,39.77 R779.1 ; v1(60.48,49.67) 60.28,49.47 C59.2 ; C73.2 65.55,47.14 v1(65.41,47) ; v1(77.47,26.35) 77.43,26.31 C105.2 ; C112.2 C113.2 78.38,28.09 v1(78.68,28.39) ; v1(76.71,24.77) 76.79,24.68 77,24.68 77.28,24.4 C103.2 ; C86.2 80.11,45.37 79.87,45.6 v1(79.41,45.6) ; C28.2 37.67,61.63 v1(37.65,61.65) ; C167.1 v1(48.01,75.95) ; v1(84.21,39.21) 84.22,39.22 C75.2 ; v1(81.91,82.04) 81.91,80.54 82.41,80.04 C602.1 ; v1(63.81,41.37) 63.77,41.41 C66.2 ; C62.2 57.4,43.82 v1(57.38,43.8) ; v1(39.37,65.23) 39.97,65.23 40.86,64.34 C600.2 ; C157.2 v1(95.88,57.28) ; C137.2 v1(73.53,66.33) ; C6.2 v1(37.97,54.48) ; v1(60.61,38.97) 60.61,38.98 59.86,39.73 C50.2 59.82,38.98 v1(59.81,38.97) 59.94,38.84 C46.2 ; J2.6 93.85,21.98 v1(93.6,22.23) ; v1(50.75,4.01) 51.9,2.86 J9.M2 50.04,2.33 v1(49.78,2.59) ; v1(39.37,55.37) 38.82,55.92 C15.2 ; v1(11.59,50.22) 12.26,49.55 R179.1 ; C102.2 C99.2 52.34,41.04 v1(51.84,40.53) ; v1(48.48,45.76) C44.2 v1(47.5,44.83) 46.97,44.3 R832.1 ; TP41.1 v1(88,49.27) ; C79.2 83.72,44.49 v1(84.21,44) ; C170.2 8.15,45.74 v1(8,45.59) ; C160.2 v1(91.19,58.17) ; C89.2 53.34,35.01 v1(53.38,34.97) ; C123.1 v1(21.59,23.88) ; U18.5 v1(89.79,61.34) ; C48.2 59.37,33.3 v1(59.37,33.09) 58.8,32.52 TP51.1 ; v1(77.81,36.81) 77.68,36.68 C81.2 ; C82.2 77.34,43.66 77.57,43.43 77.58,43.43 v1(77.81,43.2) ; C119.2 54.46,24.15 54.87,23.73 v1(54.87,23.12) ; C159.2 v1(91.19,57.02) ; C58.2 C57.2 54.23,50.67 v1(53.98,50.93) ; R103.1 v1(76.84,22.86) ; v1(85.01,45.6) 85.58,45.6 85.59,45.59 85.6,45.59 85.85,45.34 C84.2 ; R133.2 v1(56.39,12.07) ; U22.5 v1(32.76,47.62) ; C101.2 C100.2 v1(52.39,44.85) ; C181.2 v1(30.25,69.96) ; TP43.1 v1(47,5.73) ; R243.1 v1(71.12,13.84) ; C152.2 v1(90.04,69.09) ; C169.1 53.33,66.8 v1(53.72,67.19) ; C151.2 v1(89.27,67.56) ; v1(4.32,24.65) 4.44,24.77 C606.1 ; R244.1 v1(71.88,15.27) ; C118.2 v1(45.61,11.83) ; R68.1 v1(67.7,51.84) ; C165.2 v1(49.17,72.24) ; R815.1 35.79,40.69 v1(34.84,41.65) ; v1(75.45,23.38) 75.48,23.35 C106.2 ; C150.2 v1(95.25,69.22) ; C175.2 v1(16.28,40.53) ; R574.2 v1(52.07,30.51) ; C110.2 v1(77.34,18.41) ; C577.2 47.77,11.83 v1(47.75,11.81) ; C14.2 v1(43.31,57.4) ; C132.2 v1(73.53,72.14) ; C16.2 v1(50.2,60.87) ; C65.2 v1(68.08,41.91) ; R166.2 v1(55.96,67.06) ; v1(12.67,41.4) C176.2 ; C111.2 v1(76.2,18.41) ; v1(56.87,10.59) 56.79,10.52 56.79,9.82 C194.1 ; C188.2 v1(59.05,12.16) ; R250.1 v1(76.58,15.37)
  BOTTOM w0.508: J5.S2 66.75,83.85 ; J5.S2 64.54,86.06 ; J5.S2 64.54,81.64 ; 86.89,81.64 J4.S2 89.1,83.85 ; J3.S3 28.47,6.43 ; J3.S3 26.89,4.84 ; J3.S3 26.89,8.01 ; J3.S3 25.3,6.43 ; TP41.1 88.81,47.84 ; TP41.1 88,47.03 ; TP41.1 87.19,47.84 ; 42.89,72.55 TP42.1 ; TP42.1 43.71,73.37 ; TP42.1 42.08,73.37 ; TP42.1 42.89,74.18 ; 10.1,4.84 J3.S4 ; J3.S4 10.1,8.01 ; J3.S4 8.51,6.43 ; J3.S4 11.68,6.43 ; 20.85,42.99 R174.1 20.85,44.13 ; J1.2 7.63,86.11 ; J1.2 6.32,88.48 ; J1.2 6.32,83.73 ; J1.2 5.01,86.11 ; 44.01,76.2 C605.1 44.01,75.05 ; 74.28,73.09 C138.2 73.7,73.66 ; 57.48,79.49 C604.1 56.91,80.06 ; 73.09,73.01 C142.2 71.94,73.01 ; J6.S4 40.12,80.98 ; J6.S4 38.68,82.41 ; J6.S4 38.68,79.54 ; J6.S4 37.25,80.98 ; 73.75,86.06 J4.S1 71.54,83.85 ; MH7.1 91.44,78.6 ; MH7.1 91.44,73.8 ; MH7.1 89.04,76.2 ; 53.39,86.82 J5.8 ; J5.8 54.47,85.74 ; J5.8 55.55,86.82 ; J5.8 54.47,87.9 ; J5.S4 51.4,91.74 ; J5.S4 51.4,87.32 ; J5.S4 53.61,89.53 ; J5.S4 49.19,89.53 ; 14.16,23.13 R121.1 15.3,23.13 ; 8.51,22.79 J3.S1 ; J3.S1 10.1,21.2 ; J3.S1 11.68,22.79 ; J3.S1 10.1,24.37 ; J1.S1 5.32,82.91 ; J1.S1 2.77,81.61 ; J1.S1 7.87,81.61 ; J1.S1 5.32,80.3 ; J5.4 55.55,84.2 ; J5.4 54.47,83.12 ; J5.4 54.47,85.28 ; 59.57,80.1 C603.1 ; C603.1 60.14,79.52 ; C603.1 60.14,80.67 ; 33.67,2.67 MH8.1 ; MH8.1 36.07,5.07 ; MH8.1 38.47,2.67 ; 94.87,61.24 U18.1 94.87,59.08 ; 34.91,20.38 R129.2 34.91,21.53 ; 7.73,28.26 C124.1 7.73,27.11 ; J3.S2 26.89,24.37 ; J3.S2 25.3,22.79 ; J3.S2 28.47,22.79 ; 50.04,71.67 C165.2 50.61,72.24 ; 62.33,89.53 J5.S3 ; J5.S3 64.54,91.74 ; J5.S3 64.54,87.32 ; J5.S3 66.75,89.53 ; 52.72,66.23 C169.1 52.72,67.37 ; J6.S1 44.12,89.41 ; J6.S1 44.12,86.54 ; J6.S1 45.56,87.98 ; J6.S1 42.69,87.98 ; 74.4,69.15 C140.2 74.4,70.3 ; J4.8 76.82,87.9 ; J4.8 75.74,86.82 ; J4.8 76.82,85.74 ; J4.8 77.9,86.82 ; 46.19,4.53 TP43.1 ; TP43.1 47,3.72 ; TP43.1 47.81,4.53 ; 84.27,68.18 C156.2 83.12,68.18 ; 38.68,86.54 J6.S2 ; J6.S2 40.12,87.98 ; J6.S2 38.68,89.41 ; C166.2 50.75,76.26 ; C166.2 49.78,75.6 ; C166.2 48.82,76.26 ; 42.69,80.98 J6.S3 ; J6.S3 44.12,79.54 ; J6.S3 44.12,82.41 ; 86.89,87.32 J4.S3 ; J4.S3 84.68,89.53 ; J4.S3 89.1,89.53 ; J4.S3 86.89,91.74 ; 69.15,73.01 R147.2 68.01,73.01 ; 3.18,6.6 MH3.1 6.48,3.3 ; MH5.1 38.47,76.2 ; MH5.1 33.67,76.2 ; MH5.1 36.07,78.6 ; MH5.1 36.07,73.8 ; 71.54,89.53 J4.S4 ; J4.S4 73.75,87.32 ; J4.S4 75.96,89.53 ; J4.S4 73.75,91.74 ; 52.51,50.18 C58.2 53.09,50.76 ; 74.11,65.68 C137.2 72.96,65.68 ; 51.4,81.64 J5.S1 51.4,86.06 ; 2.77,90.61 J1.S2 ; J1.S2 5.32,89.3 ; J1.S2 5.32,91.91 ; J1.S2 7.87,90.61 ; J6.4 42.48,81.25 ; J6.4 40.32,81.25 ; J6.4 41.4,80.17 ; 30.1,41.87 R772.2 29.53,41.29 ; 91.44,5.07 MH6.1 89.04,2.67 ; 16.28,41.97 C175.2 16.85,41.4 ; 7.16,29.08 C125.1 7.73,28.51 ; J4.4 77.9,84.2 ; J4.4 76.82,85.28 ; J4.4 76.82,83.12 ; 70.68,73.01 C139.2 69.53,73.01 ; 10.84,40.65 C173.2 9.69,40.65
  vias: v1(1.65,89.66) v1(1.65,87.5) v1(1.78,91.69) v1(1.78,81.15) v1(1.83,15.04) v1(1.9,83.95) v1(3.3,88.52) v1(3.3,77.85) v1(3.56,8.71) v1(3.91,12.93) v1(4.06,83.82) v1(4.19,87.71) v1(4.37,33.94) v1(5.08,77.09) v1(5.56,10.72) v1(6.05,14.1) v1(6.64,33.94) v1(6.73,93.15) v1(7.24,78.36) v1(8.51,93.43) v1(9.47,25.58) v1(9.4,13.21) v1(9.79,14.67) v1(10.8,93.36) v1(10.87,18.54) v1(11.06,28.53) v1(11.81,94.5) v1(11.81,38.99) v1(11.94,41.73) v1(12.03,24.76) v1(12.42,22.11) v1(12.57,42.16) v1(13.21,93.4) v1(13.36,20.78) v1(13.43,22.28) v1(13.84,24.9) v1(14.38,21.05) v1(16.34,39.57) v1(16.56,22.68) v1(17.02,93.56) v1(17.24,21.06) v1(18.31,7.59) v1(20.07,20.78) v1(21.59,73.28) v1(22.1,72.39) v1(22.59,21.42) v1(25.07,28.33) v1(25.94,27.82) v1(26.29,96.39) v1(26.42,73.91) v1(26.42,72.9) v1(26.38,29.79) v1(26.58,32.2) v1(26.68,27.21) v1(27.43,73.91) v1(27.43,72.9) v1(27.43,71.88) v1(27.43,70.87) v1(27.42,42.48) v1(27.57,27.84) v1(27.68,29.88) v1(28.04,3.89) v1(28.21,43.06) v1(28.36,11.93) v1(28.45,72.9) v1(28.45,71.88) v1(28.45,70.87) v1(28.45,29.5) v1(28.52,9.06) v1(28.74,10.39) v1(29.1,43.01) v1(29.72,92.07) v1(29.84,8.32) v1(30.05,11.56) v1(30.15,46.74) v1(30.15,45.36) v1(30.35,96.39) v1(30.75,9.82) v1(30.73,6.93) v1(30.86,45.97) v1(31.3,43.08) v1(31.38,29.62) v1(31.55,46.74) v1(31.55,45.36) v1(31.5,8.97) v1(31.62,11.3) v1(31.65,7.47) v1(31.72,19.36) v1(31.72,4.37) v1(31.86,22.51) v1(32.29,43.06) v1(32.42,20.96) v1(33.02,78.65) v1(33.1,5.92) v1(33.53,77.84) v1(33.83,7.77) v1(34.16,69.6) v1(34.92,70.36) v1(34.92,69.6) v1(34.92,68.83) v1(35.69,69.6) v1(36.12,6.73) v1(37.59,7.47) v1(37.97,73.7) v1(38.2,6.4) v1(39.37,76.84) v1(39.37,75.08) v1(39.7,7.32) v1(40.26,91.66) v1(40.39,6.5) v1(40.77,89.46) v1(41.1,4.17) v1(41.27,2.54) v1(41.53,91.76) v1(41.91,89.62) v1(42.55,59.69) v1(42.55,58.17) v1(43.31,60.45) v1(43.31,59.69) v1(43.31,58.93) v1(43.31,58.17) v1(43.28,7.92) v1(43.76,4.29) v1(44.07,59.69) v1(44.07,58.17) v1(44.83,60.45) v1(44.83,59.69) v1(44.83,58.93) v1(44.83,58.17) v1(44.83,57.4) v1(45.09,93.47) v1(45.21,5.18) v1(45.59,59.69) v1(45.59,58.17) v1(45.72,91.73) v1(46.41,7.11) v1(46.86,93.42) v1(47.24,91.41) v1(50.29,93.28) v1(51.38,7.75) v1(52.32,79.91) v1(53.98,80.77) v1(54.74,79.77) v1(55.24,90.55) v1(55.75,89.41) v1(57.4,93.13) v1(57.91,90.81) v1(59.82,89.53) v1(60.45,76.2) v1(60.96,91.3) v1(62.1,76.2) v1(63.25,93.48) v1(66.17,86.51) v1(68.58,65.99) v1(68.71,69.34) v1(68.96,89.07) v1(69.22,83.13) v1(69.34,90.68) v1(69.34,86.49) v1(69.49,66.17) v1(69.72,69.34) v1(69.98,88.01) v1(69.98,84.58) v1(70.74,71.37) v1(70.74,70.36) v1(70.74,69.34) v1(70.74,68.33) v1(70.74,67.31) v1(70.87,65.91) v1(71.75,69.34) v1(72.24,28.47) v1(72.39,29.09) v1(72.77,69.34) v1(72.72,26.82) v1(73.36,27.07) v1(74.55,93.24) v1(76.2,52.58) v1(77.09,90.81) v1(78.1,89.53) v1(78.87,90.68) v1(79.25,75.56) v1(80.01,93.45) v1(80.22,68.56) v1(80.65,89.2) v1(82.04,90.93) v1(82.34,68.56) v1(82.42,18.24) v1(82.68,19.31) v1(82.8,89.41) v1(83.57,20.28) v1(83.57,15.86) v1(83.82,21.29) v1(84.07,52.07) v1(84.91,50.26) v1(85.6,20.75) v1(86.29,51.31) v1(86.45,50.2) v1(86.75,48.12) v1(86.74,5.33) v1(86.94,49.47) v1(87,6.48) v1(87.15,51.14) v1(87.85,46.8) v1(87.88,2.54) v1(88.32,50.38) v1(88.39,14.19) v1(88.79,42.21) v1(88.87,49.35) v1(88.95,44.16) v1(89.04,46.54) v1(89.07,45.19) v1(89.15,78.11) v1(89.17,43.13) v1(89.24,41.36) v1(89.79,34.61) v1(90.6,15.55) v1(90.81,14.58) v1(92.2,14.48) v1(92.48,7.01) v1(92.58,38.81) v1(92.62,36.93) v1(95,28.07) v1(96.14,66.29) v1(96.24,9.17) v1(96.39,11.68) v1(97.16,63.16) v1(97.59,8.23) v1(97.76,33.71) v1(97.71,32.51) v1(97.71,30.86) v1(97.69,29.41) v1(97.71,9.6) v1(98.04,87.04)
GND_DEBUGUSB_CONN: length 14.7
  TOP w0.381: J8.S4 3.93,43.56 4.03,43.46 J8.S1 ; J8.S4 J8.S5 J8.S6 J8.S3 3.93,36.96 4.03,37.06 J8.S2 ; J8.S4 2.79,44.36 2.79,44.37 R178.1 C177.1
VBUS1_FL: length 28.2
  TOP w0.381: C601.2 J4.1
  BOTTOM w0.203: 91.69,85.85 P9.2 92.37,85.13 92.33,85.09
  BOTTOM w0.508: 92.33,85.09 92.33,82.55 94.36,80.52 FB10.2 ; 91.69,85.85 91.57,85.85 90.93,86.49 86.11,86.49 J4.1
VBUS2_FL: length 22.3
  BOTTOM w0.142: P10.2 84.28,78.76 84.43,78.92
  BOTTOM w0.254: C602.2 83.44,79.9 83.54,79.8 P10.2
  BOTTOM w0.381: C602.2 83.44,82.42 82.65,83.21 82.65,85.65 J4.5
  BOTTOM w0.508: 84.43,78.92 86.18,78.92 88.14,76.96 88.14,74.55 90.91,71.77 FB11.2
VBUS3_FL: length 38.5
  BOTTOM w0.203: 62.36,78.49 62.1,78.74 61.89,78.74 61.81,78.82 P11.2
  BOTTOM w0.254: P11.2 61.15,79.24 60.94,79.45 C603.2
  BOTTOM w0.508: FB12.2 86.09,72.66 79.88,78.87 79.88,79.88 78.61,81.15 66.8,81.15 65.32,79.67 65.28,79.67 64.1,78.49 62.36,78.49 ; J5.1 61.47,83.02 60.94,82.5 C603.2
VBUS4_FL: length 40.3
  BOTTOM w0.203: P12.2 58.23,78.38 58.51,78.1 58.8,78.1
  BOTTOM w0.508: C604.2 58.28,81.01 60.2,82.93 60.2,83.69 60.2,83.69 60.2,85.55 J5.5 ; FB13.2 83.69,73.66 78.99,78.36 75.95,78.36 75.06,79.25 66.68,79.25 65.03,77.6 59.3,77.6 58.8,78.1
VBUS5_FL: length 16.8
  BOTTOM w0.254: P13.2 46.7,75.24 FB14.2
  BOTTOM w0.381: FB14.2 45.7,75.2 45.68,75.22 45.22,75.22 C605.2 44.81,79.26 45.65,80.09 45.65,83 J6.1
VBUS_DEBUG_USB_5V: length 2.9
  TOP w0.381: J8.1 7.5,41.56 FB4.1
VBUS_DET: length 4.4
  BOTTOM w0.142: U20.15 11.19,46.67 11.05,46.81 11.05,48.13 11.18,48.26 R175.2 R179.2
VBUS_DET_HUB: length 5.9
  TOP w0.142: U14.44 72.49,64.41 72.64,64.25 72.64,63.52 73.06,63.1 73.06,60.63 73.07,60.63 73.07,59.88 R140.2
VCCI_EMMC: length 5.5
  TOP w0.076: 74.72,20.96 74.72,21.65 U8.C2 75.22,21.64 75.22,21.25
  TOP w0.142: 75.22,21.25 75.31,21.15 v1(75.31,20.7) 74.86,20.7 74.72,20.84 74.72,20.96
  BOTTOM w0.381: C110.1 C111.1 76.05,19.96 v1(75.31,20.7)
VDD_1V0: length 14.2
  TOP w0.142: U1.21 43.07,62.91 42.4,63.58 42.4,68.18 42.76,68.54 C30.1 43.69,67.89 43.69,67.88 L5.2
  TOP w0.254: TP37.1 44.83,70.74 44.83,68.95 44.42,68.54 C30.1
VDD_1V8: length 180.1
  TOP w0.142: U8.N4 80.27,23.19 U8.P5 ; U8.N4 U8.P3 80.86,22.39 81.15,22.1 v1(81.17,22.1) ; U8.N4 U8.M4
  TOP w0.203: v1(75.39,24.16) 75.38,24.16 75.11,23.89 U8.C6 ; U8.P5 81.05,23.39 v1(81.28,23.62) ; U4.C2 92.08,23.36 ; v1(79.01,22.89) U8.M4
  TOP w0.254: v1(61.4,38.14) 61.4,38.18 U6.E7
  TOP w0.381: R99.1 v1(65.15,22.86) ; H4.9 H4.7 19.61,46.48 19.62,46.47 20.12,46.47 20.15,46.5 C588.1 C587.1 v1(23.01,46.5) ; v1(74.8,5.21) 74.06,5.95 FB8.1 ; R100.1 v1(65.15,26.29) ; v1(92.07,21.34) 92.69,21.95 C39.1 92.08,23.37 92.08,23.36 ; R102.1 65.66,17.14 v1(65.28,16.76) ; R101.1 v1(67.02,28.58) ; v1(65.4,18.68) 65.89,19.18 R97.1 R98.1 ; R858.1 65.15,27.43 v1(65.07,27.35) ; R94.1 v1(65.15,21.72) ; R96.1 v1(65.15,25.15) ; R95.1 v1(65.15,24)
  L3_SIG1 w0.102: v1(61.4,38.14) 61.7,37.83 61.83,37.7 61.83,36.21
  L3_SIG1 w0.254: 61.83,36.21 61.83,34.56 66.07,30.33 66.07,29.56 67.02,28.6 v1(67.02,28.58)
  L3_SIG1 w0.381: v1(46.61,48.77) 46.04,48.77 46.01,48.74 45.97,48.74 45.62,48.39 38.96,48.39 37.85,47.28 34.89,47.28 33.87,48.3 28.49,48.3 26.33,46.14 24.9,46.14 24.54,46.5 v1(23.01,46.5)
  L5_PWR w0.381: v1(46.61,48.77) 48.13,48.77 48.9,48.01 52.06,48.01 53.93,49.87 57.82,49.87 59.69,48.01 63.29,48.01 64.05,48.77 64.26,48.77 65.02,49.53 67.77,49.53 69.5,51.26 69.5,52.66 70.05,53.21 72.82,53.21 73.03,53.43 73.53,53.43 73.74,53.21 74.8,53.21 v1(75.31,52.7) ; v1(74.8,5.21) 74.8,7.26 72.06,10.01 69.24,10.01 68.24,11.01 68.24,13.6 69.6,14.96 69.6,16.13 68.96,16.76 v1(65.28,16.76) 65.28,17.34 65.4,17.45 v1(65.4,18.68)
  BOTTOM w0.142: U23.11 37.54,69.27 37.67,69.14 37.92,69.14 38.92,70.15 41.85,70.15 42.43,69.56 43.54,69.56 45.45,71.47 47.26,71.47 47.72,71.01 47.72,70.49 48.1,70.1 v1(48.26,70.1)
  BOTTOM w0.305: C113.1 C112.1 76.14,27.29 76.03,27.18 U9.8
  BOTTOM w0.381: v1(81.17,22.1) 81.15,22.1 81.13,22.08 C109.1 ; v1(75.39,24.16) 75.4,24.15 C106.1 ; C113.1 80.37,27.29 80.42,27.24 v1(80.99,27.24) 81.62,27.24 83.92,24.94 85.17,24.94 85.6,24.51 85.6,22.99 86.36,22.23 86.36,12.7 81.79,8.13 81.79,6.48 80.39,5.08 75.5,5.08 75.37,5.21 v1(74.8,5.21) ; v1(61.4,38.14) 61.61,37.93 61.83,37.93 ; R69.1 51.44,34.67 v1(51.56,34.54) ; R104.2 67.02,27.44 v1(67.02,28.58) ; C107.1 v1(81.28,23.62) ; v1(79.01,22.89) 79.01,22.88 C108.1
  vias: v1(48.26,71.12) v1(49.28,70.99) v1(49.32,69.98) v1(50.29,70.99) v1(50.29,69.98) v1(75.31,64.01) v1(76.2,64.01) v1(87.76,25.4) v1(87.88,24.51) v1(89.28,23.75)
VDD_1V8_SNS: length 13.8
  BOTTOM w0.142: U23.12 37.54,68.62 37.72,68.8 38.06,68.8 39.07,69.8 41.71,69.8 42.29,69.22 43.69,69.22 45.59,71.12 47.12,71.12 47.37,70.87 47.37,69.98 47.24,69.85 47.04,69.85 46.86,70.03 v1(46.86,70.1)
VDD_ARM_CAP: length 16.2
  TOP w0.203: U6.H11 v1(58.18,40.57) 58.57,40.18 U6.G11 v1(58.18,39.77) ; U6.G9 v1(60.61,39.77) ; U6.G10 v1(58.98,39.77)
  BOTTOM w0.142: v1(60.61,39.77) 61.01,39.37 61.01,38.81 60.58,38.37
  BOTTOM w0.203: C48.1 60.67,35.6 60.87,35.39 60.87,32.81 TP49.1 ; C47.1 58.94,38.9 59.23,38.9 59.44,38.7 59.44,37.94 59.8,37.57 C46.1 60.21,37.57 60.58,37.95 60.58,38.37
  BOTTOM w0.381: v1(58.98,39.77) 58.98,39.68 C47.1 58.58,39.37 58.18,39.76 v1(58.18,39.77) ; C48.1 60.07,36.42 59.94,36.55 C46.1
VDD_CENT_TAP_A1: length 4.8
  BOTTOM w0.381: FB17.2 28.07,16.88 28.05,16.87 C122.2 J3.7
VDD_CENT_TAP_A2: length 4.7
  BOTTOM w0.381: J3.12 21.59,18.89 C123.2 FB18.2
VDD_CENT_TAP_B1: length 7.1
  BOTTOM w0.381: FB19.2 8,26.42 8.51,26.92 8.51,27.06 8.53,27.08 C124.2 10.16,27.69 11.18,26.67 J3.14
VDD_CENT_TAP_B2: length 8.8
  BOTTOM w0.381: C125.2 8.51,29.1 FB20.2 9.12,30.21 9.14,30.23 9.4,30.23 9.78,30.61 14.06,30.61 J3.22
VDD_COINCELL_IN: length 59.4
  TOP w0.508: v1(21.72,67.18) 34.16,67.18 35.56,65.79 R11.2
  BOTTOM w0.508: BH1.1 9.4,53.15 7.71,51.47 7.71,50.89 7.24,50.42 C37.1
  BOTTOM w1.016: 17.65,74.24 18.76,74.24 20.55,72.45 20.55,70.84 21.72,69.67 v1(21.72,67.18) 21.72,58.17 16.7,53.15 BH1.1 ; BH1.3 16.19,75.12 16.26,75.18 16.32,75.12
VDD_DCDC6: length 1.1
  TOP w0.381: R13.2 38.61,68.62
VDD_DCJACK_5VIN: length 43.2
  TOP w0.635: 11.01,86.11 J1.1 ; J1.1 12.32,89.12 ; J1.1 13.63,86.11 ; J1.1 12.32,83.1
  L3_SIG1 w0.635: J1.1 13.63,86.11 ; J1.1 12.32,83.1 ; J1.1 12.32,89.12 ; J1.1 11.01,86.11
  L4_SIG2 w0.635: 12.32,83.1 J1.1 ; J1.1 12.32,89.12 ; J1.1 13.63,86.11 ; J1.1 11.01,86.11
  L5_PWR w0.635: J1.1 12.32,89.12 ; J1.1 13.63,86.11 ; J1.1 12.32,83.1 ; J1.1 11.01,86.11
  BOTTOM w0.508: 11.01,86.11 J1.1 ; J1.1 13.63,86.11 ; J1.1 12.32,83.1 ; J1.1 12.32,89.12
  vias: v1(9.02,85.09) v1(9.27,87.5) v1(9.27,82.55) v1(9.65,91.44) v1(10.41,89.66) v1(10.41,85.47) v1(10.41,83.31) v1(12.19,89.79) v1(13.97,89.79) v1(14.1,88.01) v1(14.1,85.6) v1(14.1,83.44) v1(14.86,91.44) v1(16.13,83.19)
VDD_ETH_ANA_3V3: length 3.3
  TOP w0.381: FB1.2 C116.1 40.05,20.34 v1(40.01,20.29)
  BOTTOM w0.203: U10.30 39.78,20.45 39.79,20.44 39.85,20.44 v1(40.01,20.29)
VDD_EXT_LS_5V0: length 34.7
  TOP w0.381: R189.1 v1(35.31,86.36)
  BOTTOM w0.142: U23.1 32.31,68.62 32.22,68.71 29.84,68.71 29.08,69.47 29.08,72.9 31.62,75.44 31.62,81.41 34.54,84.33 35.67,84.33 35.81,84.47 35.81,85.85 v1(35.31,86.36)
  BOTTOM w0.381: U19.7 50.67,73.03 50.65,73.04 C165.1 49.26,73.04 v1(48.9,73.41) ; v1(35.31,86.36) 35.81,86.87 v1(35.81,87.38) ; C157.1 93.34,57.28 93.22,57.4 v1(93.09,57.4)
  BOTTOM w0.508: C157.1 C158.1 93.6,59.04 U18.2
  vias: v1(34.04,86.36) v1(34.8,90.55) v1(35.05,87.38) v1(35.69,89.53) v1(35.69,88.26) v1(36.32,90.55) v1(36.58,89.15) v1(36.58,87.38) v1(36.83,85.85)
VDD_EXT_LS_5V0_SNS: length 27.3
  TOP w0.203: 32.89,82.93 32.89,82.94 U5.A1 ; U5.A1 32.38,82.55 32.51,82.42 ; U5.A1 U5.B1 32.89,83.44
  TOP w0.381: R189.2 v1(35.31,82.17)
  BOTTOM w0.142: v1(35.31,82.17) 35.93,82.17 36.07,82.31 36.07,83.44 35.56,83.95 34.65,83.95 31.97,81.26 31.97,75.29 29.43,72.75 29.43,69.61 29.99,69.05 31.84,69.05 32.06,69.27 U23.2
VDD_HIGH_CAP: length 16.6
  TOP w0.203: U6.N6 v1(63.01,45.4) ; U6.R15 55.4,46.61 v1(55.78,47) U6.R14
  BOTTOM w0.142: 54.72,49.38 56.01,50.67 56.01,51.69 55.24,52.45 TP52.1 ; C72.1 61.81,47.61 61.81,46.03 62.05,45.8 62.61,45.8 v1(63.01,45.4)
  BOTTOM w0.203: 54.72,49.38 C57.1 C58.1
  BOTTOM w0.254: C58.1 53.09,48.26 53.45,47.9 54.88,47.9 v1(55.78,47)
VDD_HIGH_IN_3V3: length 65.3
  TOP w0.142: 30.1,41.15 30.09,41.14 ; U1.39 42.67,54.72 42.05,54.1 42.05,50.56 40.64,49.15 40.64,47.26 41.27,46.63 v1(41.27,45.59)
  TOP w0.178: U1.31 40.46,58.73 40.17,59.02 v1(39.75,59.02)
  TOP w0.203: 90.3,23.75 U4.A2 ; U3.A2 U3.B2 30.73,40.26 ; U3.A2 30.85,40.76 30.86,40.77 ; U3.A2 30.09,41.14 ; U6.N13 v1(56.58,45.4)
  TOP w0.381: R28.2 v1(51.05,67.56) ; v1(88.09,21.55) 88.09,23.45 89.26,24.62 C40.1 89.92,24.13 90.3,23.75 ; v1(88.76,21.57) R34.2 ; v1(88.14,18.03) 88.9,18.8 R35.2
  L5_PWR w0.152: 35.56,42.55 36.2,43.18 36.2,45.47 36.58,45.85 40.56,45.85 40.82,45.59 v1(41.27,45.59)
  BOTTOM w0.142: v1(37.85,44.96) 37.85,46.38 37.99,46.52 39.73,46.52 40.42,45.83 40.42,44.47 39.48,43.53 37.48,43.53 35.14,45.86 35.14,48.15 33.75,49.55 33.75,50.56 33.16,51.15 30.72,51.15 29.88,50.31 29.88,48.88 29.89,48.87 U22.1 ; 54.74,45.79 55.95,45.79 56.35,45.4 v1(56.58,45.4)
  BOTTOM w0.254: C56.1 C55.1 54.52,45.57 54.74,45.79
  BOTTOM w0.381: C27.1 47.68,58.13 47.71,58.16 v1(48.28,58.16) ; C28.1 v1(39.75,59.02)
  vias: v1(28.58,59.56) v1(28.58,58.8) v1(29.46,59.56) v1(29.46,58.8) v1(31.37,40.77) v1(31.37,40.13) v1(37.85,44.2) v1(38.61,44.96) v1(38.61,44.2) v1(39.37,44.96) v1(39.37,44.2)
VDD_HIGH_IN_3V3_SNS: length 25.7
  TOP w0.142: v1(37.6,47.88) 37.6,48 37.75,48.14 R188.2
  BOTTOM w0.142: v1(37.6,47.88) 38.62,46.86 39.88,46.86 40.77,45.97 40.77,44.32 39.62,43.18 37.34,43.18 34.8,45.72 34.8,48.01 33.4,49.4 33.4,50.42 33.02,50.8 30.86,50.8 30.23,50.16 30.23,49.02 30.54,48.71 U22.2
VDD_HUB_LED: length 5.9
  TOP w0.381: DA3.1 v1(66.28,96.63) ; DA5.1 v1(34.53,96.63) ; DA1.1 v1(88.63,96.63) ; DA2.1 v1(69.71,96.63) ; DA4.1 v1(47.23,96.63)
  BOTTOM w0.508: D9.1 87.4,96.64 ; D9.1 86.08,96.64 ; D9.1 86.74,97.2
VDD_IN_BU: length 5.6
  TOP w0.254: U1.27 v1(40.14,60.33)
  BOTTOM w0.381: v1(40.14,60.33) 40.86,61.06 C600.1 40.44,62.04 39.24,63.24 R12.1
VDD_LCD: length 12.8
  TOP w0.254: v1(60.69,3.45) 59.56,4.58 R190.2
  TOP w0.381: R190.2 60.17,4.93 60.25,5.01 Q4.3 62.45,5.01 C182.1 C185.1
  L5_PWR w0.381: v1(60.69,3.45) 60.08,2.84 56.98,2.84 v1(56.3,3.53)
  BOTTOM w0.254: J9.34 57,4.24 v1(56.3,3.53)
VDD_LCD_BCKLIGHT: length 15.7
  TOP w0.254: C199.1 81.17,4.97 81.59,5.39 Q6.3 81.59,6.74 81.51,6.82 R261.2
  TOP w0.381: v1(79.5,5.71) C199.1 C197.1
  L5_PWR w0.381: v1(79.5,5.71) 76.86,3.07 73.3,3.07 v1(72.9,3.47)
  BOTTOM w0.254: J9.3 72.5,4.31 72.59,4.22 72.59,3.78 v1(72.9,3.47)
VDD_LCD_SW_IN: length 5.8
  TOP w0.142: 60.18,5.66 Q4.2 60.78,5.89 60.56,6.12 R192.1
  TOP w0.254: 60.18,5.66 60.11,5.73 R190.1
  TOP w0.381: C184.1 59.46,6.48 FB7.2 FB9.2
  TOP w0.508: C184.1 R190.1
VDD_LDO_2V8: length 26.1
  TOP w0.254: v1(56.72,6.1) 57.1,6.48 FB7.1
  L5_PWR w0.508: v1(56.72,6.1) 68.02,6.1 69.57,4.55 76.58,4.55 v1(79.86,7.82)
  vias: v1(55.24,58.9) v1(55.24,58.17)
VDD_NVCC_3V3: length 357
  TOP w0.142: 40.41,59.37 40.64,59.13 U1.30
  TOP w0.203: C26.1 39.72,60.05 40.41,59.37
  TOP w0.254: U6.H13 v1(56.58,40.57) ; U6.L13 v1(56.58,43.8) ; C573.1 90.24,80.6 U26.4 ; U6.M13 v1(56.58,44.6) ; U6.F13 v1(56.58,38.97) ; U6.J13 v1(56.58,41.37) ; U6.F4 v1(64.61,38.97)
  TOP w0.381: v1(94.62,85.47) 94.38,85.71 U27.5 94.92,86.4 95.2,86.13 R874.1 ; R581.1 17.02,52.9 16.64,52.51 v1(16.64,51.94) ; TP39.1 35.43,60.07 v1(36.32,60.07) ; v1(20.7,66.8) 20.07,66.8 19.07,67.8 R580.1 ; R208.1 95.1,59.92 95.84,60.67 96.69,60.67 97.03,60.32 v1(97.28,60.32) ; R138.1 v1(69.47,61.69) ; R868.1 11.41,44.55 11.28,44.68 R867.1 v1(10.14,47.37) ; R870.1 v1(74.55,56.77) ; v1(37.1,60.05) C29.1 C26.1 ; v1(23.11,47.37) 23.75,46.74 R869.1 ; R204.1 v1(93.85,52.07) ; v1(96.79,40.12) DA6.1 DA6.2 ; D15.1 v1(96.84,35.24) ; R137.1 v1(70.61,61.69) ; U2.1 54.65,62.03 54.74,62.11 R16.1 55.35,62.72 v1(55.5,62.87) ; R578.1 94.62,80.39 v1(95.12,79.88) ; v1(88.52,79.76) 89.66,79.76 90.06,80.16 C573.1
  L3_SIG1 w0.381: v1(74.55,56.77) 74.55,58.09 73.71,58.93 73.37,58.93 v1(70.61,61.69)
  L4_SIG2 w0.381: v1(37.1,60.05) 37.83,60.05 39.84,62.06 47.71,62.06 48.9,63.25 54.55,63.25 54.93,62.87 v1(55.5,62.87) 56.77,64.13 56.77,66.8 v1(58.17,68.2) 56.39,69.98 v1(56.39,76.07) ; v1(43.31,36.45) 43.31,37.24 43.83,37.76 49.36,37.76 v1(50.25,36.86) ; v1(91.31,46.61) 90.53,45.83 90.53,41.99 90.45,41.91 90.45,33.26 90.26,33.06 90.26,30.16 89.52,29.42 81.78,29.42 81.05,30.15 80.6,30.15 80.56,30.19 77.89,30.19 74.67,33.41 72.78,33.41 71.81,32.44 70.34,32.44 69.47,33.31 69.47,35.23 v1(69.05,35.65) ; 19.56,48.77 18.46,49.87 18.28,49.87 17.04,51.11 17.04,51.54 v1(16.64,51.94) 16.23,52.35 11.33,52.35 10.29,51.31 10.29,48.09 10.14,47.94 v1(10.14,47.37) ; v1(88.52,79.76) 89.17,80.41 89.17,82.44 91.69,84.96 94.11,84.96 v1(94.62,85.47) 96.35,83.73 96.35,81.11 v1(95.12,79.88) 97.79,77.22 97.79,60.83 v1(97.28,60.32)
  L5_PWR w0.381: v1(96.84,35.24) 96.84,35.81 96.79,35.86 v1(96.79,40.12) ; 40.96,38.61 v1(35.81,38.61) ; v1(55.5,62.87) 55.9,62.46 55.9,62.21 57.5,60.61 64.3,60.61 64.6,60.92 66.59,60.92 66.86,60.65 68.43,60.65 v1(69.47,61.69) v1(70.61,61.69) 71.34,60.96 73.91,60.96 74.51,61.56 82.46,61.56 83.44,60.58 84.33,60.58 85.34,59.56 88.77,59.56 90.17,58.17 90.17,55.75 v1(93.85,52.07) ; 41.32,38.64 41.32,38.1 41.92,37.5 42.25,37.5 v1(43.31,36.45) ; v1(93.85,52.07) 96.79,49.13 v1(96.79,40.12) ; v1(93.85,52.07) 97.28,55.5 v1(97.28,60.32) ; v1(96.79,40.12) 95.01,40.12 92.84,42.29 92.84,45.09 v1(91.31,46.61) ; v1(20.7,66.8) 18.67,66.8 18.03,66.17 18.03,53.34 v1(16.64,51.94)
  BOTTOM w0.142: v1(64.61,38.97) 65.01,38.57 65.66,38.57 ; v1(56.58,38.97) 56.98,39.37 56.98,40.15 56.86,40.28 56.86,40.3 v1(56.58,40.57) ; v1(56.58,40.57) 56.19,40.97 54.82,40.97 54.09,40.24 C102.1 53.92,40.17 56.17,40.17 56.57,40.57 v1(56.58,40.57) ; v1(56.58,44.6) 56.19,45 55.42,45 54.9,44.48 55.18,44.19 56.19,44.19 v1(56.58,43.8)
  BOTTOM w0.254: 65.66,38.57 65.87,38.35 66.04,38.35 66.29,38.1 C96.1 ; C101.1 54.47,44.05 54.9,44.48 ; v1(56.58,41.37) 56.87,41.09 C91.1 56.87,40.85 v1(56.58,40.57) ; v1(56.58,43.8) v1(56.58,44.6)
  BOTTOM w0.381: v1(69.05,35.65) 67.85,35.65 67.05,36.45 67.05,37.6 66.78,37.87 C96.1 ; 29.34,38.35 29.34,38.4 30.05,39.12 R840.1 ; 29.34,38.35 28.77,38.35 28.23,37.82 28.23,35.69 29.47,34.46 31.27,34.46 31.52,34.21 32.01,34.21 32.26,34.46 32.93,34.46 35.81,37.34 v1(35.81,38.61) 35.79,38.63 R814.1 ; 29.34,38.35 29.34,37.62 29.96,37 30.07,37 30.23,36.83 R839.1 ; R70.1 50.63,36.48 v1(50.25,36.86) ; v1(43.31,36.45) 42.93,36.83 R25.2 ; v1(26.29,48.9) 26.67,48.9 27.2,49.42 R182.1 R181.1 ; C99.1 C102.1 ; R86.1 v1(56.39,76.07) ; R871.1 64.45,54.38 63.18,55.65 R866.1 60.45,55.65 55.5,60.59 v1(55.5,62.87) ; C100.1 C101.1 ; R164.1 v1(58.17,68.2)
  vias: v1(23.88,49.66) v1(25.53,48.77)
VDD_NVCC_SD1: length 13.4
  TOP w0.203: 91.19,23.88 U4.B2 ; U6.C4 v1(64.61,36.57)
  TOP w0.381: 91.19,23.88 C42.1 91.93,24.62 91.95,24.64 ; 92.71,25.08 92.71,27.81
  BOTTOM w0.381: R72.1 87,29.46 87.25,29.72 v1(87.25,31.69) ; 66.01,34.42 64.88,35.54 C92.1 64.88,36.3 v1(64.61,36.57) ; R76.1 v1(85.72,31.5) ; R73.1 v1(89.66,31.62) ; R74.1 v1(90.93,31.62)
VDD_OTG1_VBUS: length 5.3
  BOTTOM w0.381: FB3.1 50.9,66.78 50.92,66.8 C169.2 51.88,66.84 C168.1 51.88,69.46 51.89,69.46 U19.5
